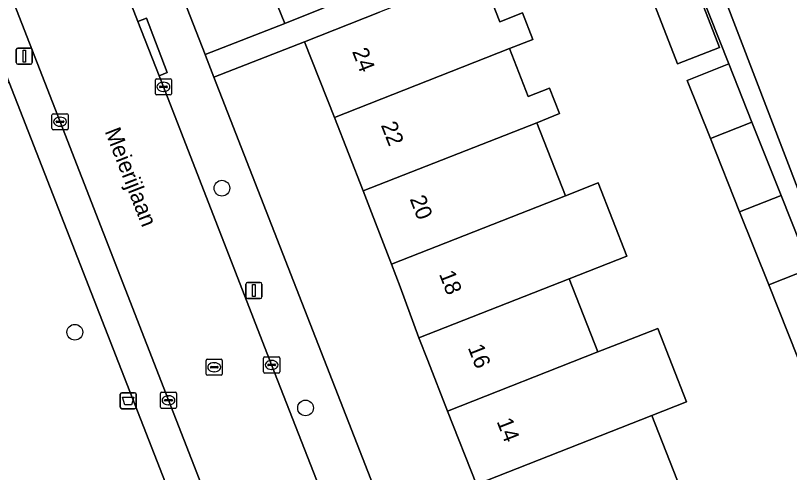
# Model space of a CAD drawing. Extents: x 159680 to 160786, y 387323 to 388340.
# Drawn here: x 160044.77 to 160092.86, y 387434.59 to 387462.98 of the extents above; entities that cross this region are included whole.
import ezdxf

# ---------------------------------------------------------------- set-up
doc = ezdxf.new("R2010")
doc.units = 0
for name, color, linetype in [('IMGEO_Afvalbak', 7, 'Continuous'), ('IMGEO_Boom', 7, 'Continuous'), ('IMGEO_Erf', 7, 'Continuous'), ('IMGEO_Groenvoorziening', 7, 'Continuous'), ('IMGEO_Kolk', 7, 'Continuous'), ('IMGEO_Lichtmast', 7, 'Continuous'), ('IMGEO_Muur', 7, 'Continuous'), ('IMGEO_Openbare_ruimte_label', 7, 'Continuous'), ('IMGEO_Pand', 7, 'Continuous'), ('IMGEO_Pand_nummerreeks', 7, 'Continuous'), ('IMGEO_Rijbaan_lokaal_open', 7, 'Continuous'), ('IMGEO_Rioolput', 7, 'Continuous'), ('IMGEO_Voetpad_open', 7, 'Continuous')]:
    doc.layers.add(name, color=color, linetype=linetype)

msp = doc.modelspace()

# ---------------------------------------------------------------- linework, layer by layer
at = {"layer": 'IMGEO_Afvalbak'}
for p, q in [((160051.283, 387438.647), (160051.283, 387439.447)), ((160051.283, 387439.447), (160051.283, 387438.647)), ((160051.383, 387439.547), (160052.173, 387439.547)), ((160052.173, 387439.547), (160051.383, 387439.547)), ((160052.273, 387439.447), (160052.273, 387438.647)), ((160052.273, 387438.647), (160052.273, 387439.447)), ((160052.173, 387438.547), (160051.383, 387438.547)), ((160051.383, 387438.547), (160052.173, 387438.547))]:
    msp.add_line(p, q, dxfattribs=at)
msp.add_lwpolyline([(160051.426, 387439.261), (160052.13, 387439.261), (160051.981, 387438.791), (160051.575, 387438.791), (160051.426, 387439.261)], dxfattribs=at)
for centre, start, end in [((160051.383, 387439.447), 90, 180), ((160051.383, 387439.447), 90, 180), ((160052.173, 387439.447), 0, 90), ((160052.173, 387439.447), 360, 90), ((160051.383, 387438.647), 180, 270), ((160051.383, 387438.647), 180, 270), ((160052.173, 387438.647), 270, 0), ((160052.173, 387438.647), 270, 0)]:
    msp.add_arc(centre, 0.1, start, end, dxfattribs=at)
at = {"layer": 'IMGEO_Boom'}
for centre in [(160057.598, 387452.249), (160048.46, 387443.302), (160062.793, 387438.599)]:
    msp.add_circle(centre, 0.489, dxfattribs=at)
at = {"layer": 'IMGEO_Erf'}
for points in [[(160098.383, 387501.774), (160097.114, 387501.273), (160093.888, 387500), (160077.508, 387493.535), (160099.139, 387437.225), (160113.969, 387443.3), (160122.048, 387446.454)], [(160048.858, 387480.25), (160049.768, 387477.92), (160056.549, 387460.554), (160061.498, 387462.487), (160060.179, 387465.75), (160064.86, 387467.643), (160067.322, 387468.638), (160068.641, 387465.375), (160078.623, 387469.308), (160084.48, 387471.518), (160084.359, 387471.814), (160081.27, 387470.546), (160080.225, 387473.092), (160083.461, 387474.421), (160080.976, 387480.847)], [(160093.377, 387441.71), (160091.567, 387446.251), (160089.758, 387450.79), (160087.948, 387455.331), (160086.507, 387458.947), (160089.08, 387459.972), (160084.957, 387470.364)], [(160073.663, 387465.65), (160074.866, 387462.591), (160076.272, 387463.144), (160076.921, 387461.494), (160075.46, 387460.919), (160076.629, 387457.948), (160077.938, 387458.463), (160078.558, 387456.886), (160077.156, 387456.299), (160078.932, 387451.781), (160080.968, 387452.582), (160082.759, 387448.036), (160079.171, 387446.623), (160080.959, 387442.075), (160082.508, 387442.685), (160084.67, 387443.536), (160086.46, 387438.988), (160084.296, 387438.136), (160086.084, 387433.588), (160087.805, 387429.211), (160087.872, 387429.04), (160088.826, 387426.615), (160094.321, 387428.778)], [(160073.404, 387433.849), (160071.616, 387438.397), (160070.387, 387441.537), (160069.833, 387442.947), (160068.677, 387446.123), (160068.125, 387447.526), (160066.897, 387450.749), (160066.37, 387452.088), (160064.582, 387456.636), (160062.728, 387461.35), (160057.097, 387459.151), (160078.812, 387403.541), (160078.867, 387403.411)]]:
    msp.add_lwpolyline(points, dxfattribs=at)
msp.add_lwpolyline([(160084.194, 387464.358), (160082.449, 387468.851), (160085.063, 387469.866), (160086.804, 387465.385), (160088.515, 387460.98), (160085.901, 387459.965)], close=True, dxfattribs=at)
at = {"layer": 'IMGEO_Groenvoorziening'}
msp.add_lwpolyline([(160070.819, 387394.075), (160067.983, 387398.729), (160067.343, 387400.014), (160044.382, 387458.812), (160038.002, 387456.318), (160019.905, 387500)], dxfattribs=at)
at = {"layer": 'IMGEO_Kolk'}
for p, q in [((160053.464, 387458.119), (160053.464, 387458.971)), ((160053.539, 387459.045), (160054.391, 387459.045)), ((160054.465, 387458.971), (160054.465, 387458.119)), ((160053.723, 387458.539), (160053.723, 387458.551)), ((160054.161, 387458.502), (160053.763, 387458.502)), ((160053.766, 387458.588), (160054.164, 387458.588)), ((160053.952, 387458.825), (160053.977, 387458.825)), ((160054.207, 387458.551), (160054.207, 387458.539)), ((160054.391, 387458.045), (160053.539, 387458.045)), ((160053.975, 387458.265), (160053.95, 387458.265)), ((160047.042, 387455.951), (160047.042, 387456.803)), ((160047.117, 387456.877), (160047.969, 387456.877)), ((160047.53, 387456.657), (160047.555, 387456.657)), ((160048.043, 387456.803), (160048.043, 387455.951)), ((160047.301, 387456.371), (160047.301, 387456.383)), ((160047.739, 387456.334), (160047.341, 387456.334)), ((160047.344, 387456.42), (160047.742, 387456.42)), ((160047.553, 387456.097), (160047.528, 387456.097)), ((160047.785, 387456.383), (160047.785, 387456.371)), ((160047.969, 387455.877), (160047.117, 387455.877)), ((160060.185, 387440.843), (160060.185, 387441.695)), ((160060.26, 387441.769), (160061.112, 387441.769)), ((160060.673, 387441.549), (160060.698, 387441.549)), ((160061.186, 387441.695), (160061.186, 387440.843)), ((160060.444, 387441.263), (160060.444, 387441.275)), ((160060.882, 387441.226), (160060.484, 387441.226)), ((160060.487, 387441.312), (160060.885, 387441.312)), ((160060.928, 387441.275), (160060.928, 387441.263)), ((160061.112, 387440.769), (160060.26, 387440.769)), ((160060.696, 387440.989), (160060.671, 387440.989)), ((160053.778, 387438.649), (160053.778, 387439.501)), ((160053.853, 387439.575), (160054.705, 387439.575)), ((160054.08, 387439.118), (160054.478, 387439.118)), ((160054.266, 387439.355), (160054.291, 387439.355)), ((160054.779, 387439.501), (160054.779, 387438.649)), ((160054.037, 387439.069), (160054.037, 387439.081)), ((160054.475, 387439.032), (160054.077, 387439.032)), ((160054.289, 387438.795), (160054.264, 387438.795)), ((160054.521, 387439.081), (160054.521, 387439.069)), ((160054.705, 387438.575), (160053.853, 387438.575))]:
    msp.add_line(p, q, dxfattribs=at)
for points in [[(160053.464, 387458.119), (160053.464, 387458.971)], [(160053.539, 387459.045), (160054.391, 387459.045)], [(160054.465, 387458.971), (160054.465, 387458.119)], [(160054.391, 387458.045), (160053.539, 387458.045)], [(160047.042, 387455.951), (160047.042, 387456.803)], [(160047.117, 387456.877), (160047.969, 387456.877)], [(160048.043, 387456.803), (160048.043, 387455.951)], [(160047.969, 387455.877), (160047.117, 387455.877)], [(160060.185, 387440.843), (160060.185, 387441.695)], [(160060.26, 387441.769), (160061.112, 387441.769)], [(160061.186, 387441.695), (160061.186, 387440.843)], [(160061.112, 387440.769), (160060.26, 387440.769)], [(160053.778, 387438.649), (160053.778, 387439.501)], [(160053.853, 387439.575), (160054.705, 387439.575)], [(160054.779, 387439.501), (160054.779, 387438.649)], [(160054.705, 387438.575), (160053.853, 387438.575)]]:
    msp.add_lwpolyline(points, dxfattribs=at)
for centre, radius, start, end in [((160053.541, 387458.969), 0.0765, 91.552, 178.448), ((160053.541, 387458.969), 0.0765, 91.552, 178.448), ((160054.389, 387458.969), 0.0765, 1.552, 88.448), ((160054.389, 387458.969), 0.0765, 1.552, 88.448), ((160053.763, 387458.548), 0.0403, 85.8775, 175.7526), ((160053.76, 387458.538), 0.0366, 178.938, 274.7102), ((160054.164, 387458.545), 0.043, 264.8664, 352.4533), ((160054.168, 387458.55), 0.0386, 1.7309, 96.639), ((160053.541, 387458.121), 0.0765, 181.552, 268.448), ((160053.541, 387458.121), 0.0765, 181.552, 268.448), ((160054.389, 387458.121), 0.0765, 271.552, 358.448), ((160054.389, 387458.121), 0.0765, 271.552, 358.448), ((160047.119, 387456.801), 0.0765, 91.552, 178.448), ((160047.119, 387456.801), 0.0765, 91.552, 178.448), ((160047.967, 387456.801), 0.0765, 1.552, 88.448), ((160047.967, 387456.801), 0.0765, 1.552, 88.448), ((160047.119, 387455.953), 0.0765, 181.552, 268.448), ((160047.119, 387455.953), 0.0765, 181.552, 268.448), ((160047.341, 387456.38), 0.0403, 85.8775, 175.7526), ((160047.338, 387456.37), 0.0366, 178.938, 274.7102), ((160047.742, 387456.377), 0.043, 264.8664, 352.4533), ((160047.746, 387456.382), 0.0386, 1.7309, 96.639), ((160047.967, 387455.953), 0.0765, 271.552, 358.448), ((160047.967, 387455.953), 0.0765, 271.552, 358.448), ((160060.262, 387441.693), 0.0765, 91.552, 178.448), ((160060.262, 387441.693), 0.0765, 91.552, 178.448), ((160061.11, 387441.693), 0.0765, 1.552, 88.448), ((160061.11, 387441.693), 0.0765, 1.552, 88.448), ((160060.484, 387441.272), 0.0403, 85.8775, 175.7526), ((160060.481, 387441.262), 0.0366, 178.938, 274.7102), ((160060.885, 387441.269), 0.043, 264.8664, 352.4533), ((160060.889, 387441.274), 0.0386, 1.7309, 96.639), ((160060.262, 387440.845), 0.0765, 181.552, 268.448), ((160060.262, 387440.845), 0.0765, 181.552, 268.448), ((160061.11, 387440.845), 0.0765, 271.552, 358.448), ((160061.11, 387440.845), 0.0765, 271.552, 358.448), ((160053.855, 387439.499), 0.0765, 91.552, 178.448), ((160053.855, 387439.499), 0.0765, 91.552, 178.448), ((160054.077, 387439.078), 0.0403, 85.8775, 175.7526), ((160054.482, 387439.08), 0.0386, 1.7309, 96.639), ((160054.703, 387439.499), 0.0765, 1.552, 88.448), ((160054.703, 387439.499), 0.0765, 1.552, 88.448), ((160053.855, 387438.651), 0.0765, 181.552, 268.448), ((160053.855, 387438.651), 0.0765, 181.552, 268.448), ((160054.074, 387439.068), 0.0366, 178.938, 274.7102), ((160054.478, 387439.075), 0.043, 264.8664, 352.4533), ((160054.703, 387438.651), 0.0765, 271.552, 358.448), ((160054.703, 387438.651), 0.0765, 271.552, 358.448)]:
    msp.add_arc(centre, radius, start, end, dxfattribs=at)
for centre, major_axis, ratio, start_param, end_param in [((160053.951, 387458.545), (-0.387, 0.002), 0.722429, 4.712389, 7.853982), ((160053.976, 387458.545), (-0.39, 0.002), 0.717154, 1.570796, 4.712389), ((160047.529, 387456.377), (-0.387, 0.002), 0.722429, 4.712389, 7.853982), ((160047.554, 387456.377), (-0.39, 0.002), 0.717154, 1.570796, 4.712389), ((160060.672, 387441.269), (-0.387, 0.002), 0.722429, 4.712389, 7.853982), ((160060.697, 387441.269), (-0.39, 0.002), 0.717154, 1.570796, 4.712389), ((160054.265, 387439.075), (-0.387, 0.002), 0.722429, 4.712389, 7.853982), ((160054.29, 387439.075), (-0.39, 0.002), 0.717154, 1.570796, 4.712389)]:
    msp.add_ellipse(centre, major_axis=major_axis, ratio=ratio, start_param=start_param, end_param=end_param, dxfattribs=at)
at = {"layer": 'IMGEO_Lichtmast'}
for p, q in [((160044.826, 387460.054), (160044.826, 387460.854)), ((160044.826, 387460.854), (160044.826, 387460.054)), ((160044.926, 387460.954), (160045.716, 387460.954)), ((160045.716, 387460.954), (160044.926, 387460.954)), ((160045.816, 387460.854), (160045.816, 387460.054)), ((160045.816, 387460.054), (160045.816, 387460.854)), ((160045.716, 387459.954), (160044.926, 387459.954)), ((160044.926, 387459.954), (160045.716, 387459.954)), ((160059.187, 387446.395), (160059.977, 387446.395)), ((160059.977, 387446.395), (160059.187, 387446.395)), ((160059.087, 387445.495), (160059.087, 387446.295)), ((160059.087, 387446.295), (160059.087, 387445.495)), ((160060.077, 387446.295), (160060.077, 387445.495)), ((160060.077, 387445.495), (160060.077, 387446.295)), ((160059.977, 387445.395), (160059.187, 387445.395)), ((160059.187, 387445.395), (160059.977, 387445.395))]:
    msp.add_line(p, q, dxfattribs=at)
for points in [[(160045.246, 387460.829), (160045.396, 387460.829), (160045.396, 387460.079), (160045.246, 387460.079), (160045.246, 387460.829)], [(160059.507, 387446.27), (160059.657, 387446.27), (160059.657, 387445.52), (160059.507, 387445.52), (160059.507, 387446.27)]]:
    msp.add_lwpolyline(points, dxfattribs=at)
for centre, start, end in [((160044.926, 387460.854), 90, 180), ((160044.926, 387460.854), 90, 180), ((160045.716, 387460.854), 0, 90), ((160045.716, 387460.854), 360, 90), ((160044.926, 387460.054), 180, 270), ((160044.926, 387460.054), 180, 270), ((160045.716, 387460.054), 270, 0), ((160045.716, 387460.054), 270, 0), ((160059.187, 387446.295), 90, 180), ((160059.187, 387446.295), 90, 180), ((160059.977, 387446.295), 0, 90), ((160059.977, 387446.295), 360, 90), ((160059.187, 387445.495), 180, 270), ((160059.187, 387445.495), 180, 270), ((160059.977, 387445.495), 270, 0), ((160059.977, 387445.495), 270, 0)]:
    msp.add_arc(centre, 0.1, start, end, dxfattribs=at)
at = {"layer": 'IMGEO_Muur'}
msp.add_lwpolyline([(160049.768, 387477.92), (160056.549, 387460.554), (160056.572, 387460.495)], dxfattribs=at)
at = {"layer": 'IMGEO_Pand'}
for points in [[(160064.86, 387467.643), (160060.179, 387465.75), (160061.498, 387462.487), (160066.142, 387464.364)], [(160076.272, 387463.144), (160074.866, 387462.591), (160073.663, 387465.65), (160067.382, 387463.18), (160062.728, 387461.35), (160064.582, 387456.636), (160075.46, 387460.919), (160076.921, 387461.494)], [(160086.804, 387465.385), (160084.194, 387464.358), (160085.901, 387459.965), (160088.515, 387460.98)], [(160078.558, 387456.886), (160077.938, 387458.463), (160076.629, 387457.948), (160075.46, 387460.919), (160064.582, 387456.636), (160066.37, 387452.088), (160077.156, 387456.299)], [(160087.948, 387455.331), (160090.525, 387456.346), (160089.08, 387459.972), (160086.507, 387458.947)], [(160066.37, 387452.088), (160066.897, 387450.749), (160068.125, 387447.526), (160078.932, 387451.781), (160077.156, 387456.299)], [(160090.525, 387456.346), (160087.948, 387455.331), (160089.758, 387450.79), (160092.335, 387451.805)], [(160080.968, 387452.582), (160078.932, 387451.781), (160068.125, 387447.526), (160068.677, 387446.123), (160069.833, 387442.947), (160079.171, 387446.623), (160082.759, 387448.036)], [(160092.335, 387451.805), (160089.758, 387450.79), (160091.567, 387446.251), (160094.144, 387447.266)], [(160094.144, 387447.266), (160091.567, 387446.251), (160093.377, 387441.71), (160095.954, 387442.725)], [(160079.171, 387446.623), (160069.833, 387442.947), (160070.387, 387441.537), (160071.616, 387438.397), (160080.959, 387442.075)], [(160086.46, 387438.988), (160084.67, 387443.536), (160082.508, 387442.685), (160080.959, 387442.075), (160071.616, 387438.397), (160073.404, 387433.849), (160084.296, 387438.136)], [(160073.404, 387433.849), (160075.193, 387429.301), (160086.084, 387433.588), (160084.296, 387438.136)]]:
    msp.add_lwpolyline(points, close=True, dxfattribs=at)
at = {"layer": 'IMGEO_Rijbaan_lokaal_open'}
for points in [[(160046.513, 387477.713), (160045.765, 387479.734), (160039.549, 387495.628), (160039.516, 387495.711), (160039.429, 387495.946), (160033.273, 387511.651), (160031.95, 387515.027), (160031.202, 387516.934), (160024.093, 387535.131), (160021.109, 387542.72), (160014.836, 387540.165), (160017.868, 387532.491), (160033.182, 387493.23), (160040.063, 387475.562), (160047.543, 387456.377), (160054.279, 387439.075), (160061.763, 387419.918), (160069.174, 387400.967), (160069.426, 387400.286), (160069.653, 387399.763)], [(160075.587, 387403.186), (160068.134, 387422.235), (160060.686, 387441.269), (160053.965, 387458.545), (160053.696, 387459.237), (160052.383, 387462.613), (160046.513, 387477.713)]]:
    msp.add_lwpolyline(points, dxfattribs=at)
at = {"layer": 'IMGEO_Rioolput'}
for p, q in [((160056.619, 387440.703), (160056.619, 387441.555)), ((160056.694, 387441.629), (160057.546, 387441.629)), ((160057.62, 387441.555), (160057.62, 387440.703)), ((160056.878, 387441.123), (160056.878, 387441.135)), ((160057.316, 387441.086), (160056.918, 387441.086)), ((160056.921, 387441.172), (160057.319, 387441.172)), ((160057.107, 387441.409), (160057.132, 387441.409)), ((160057.362, 387441.135), (160057.362, 387441.123)), ((160057.546, 387440.629), (160056.694, 387440.629)), ((160057.13, 387440.849), (160057.105, 387440.849))]:
    msp.add_line(p, q, dxfattribs=at)
for points in [[(160056.619, 387440.703), (160056.619, 387441.555)], [(160056.694, 387441.629), (160057.546, 387441.629)], [(160057.62, 387441.555), (160057.62, 387440.703)], [(160057.546, 387440.629), (160056.694, 387440.629)]]:
    msp.add_lwpolyline(points, dxfattribs=at)
for centre, radius, start, end in [((160056.696, 387441.553), 0.0765, 91.552, 178.448), ((160056.696, 387441.553), 0.0765, 91.552, 178.448), ((160057.544, 387441.553), 0.0765, 1.552, 88.448), ((160057.544, 387441.553), 0.0765, 1.552, 88.448), ((160056.918, 387441.132), 0.0403, 85.8775, 175.7526), ((160056.915, 387441.122), 0.0366, 178.938, 274.7102), ((160057.319, 387441.129), 0.043, 264.8664, 352.4533), ((160057.323, 387441.134), 0.0386, 1.7309, 96.639), ((160056.696, 387440.705), 0.0765, 181.552, 268.448), ((160056.696, 387440.705), 0.0765, 181.552, 268.448), ((160057.544, 387440.705), 0.0765, 271.552, 358.448), ((160057.544, 387440.705), 0.0765, 271.552, 358.448)]:
    msp.add_arc(centre, radius, start, end, dxfattribs=at)
for centre, major_axis, ratio, start_param, end_param in [((160057.106, 387441.129), (-0.387, 0.002), 0.722429, 4.712389, 7.853982), ((160057.131, 387441.129), (-0.39, 0.002), 0.717154, 1.570796, 4.712389)]:
    msp.add_ellipse(centre, major_axis=major_axis, ratio=ratio, start_param=start_param, end_param=end_param, dxfattribs=at)
at = {"layer": 'IMGEO_Voetpad_open'}
for points in [[(160014.836, 387540.165), (160013.589, 387543.411), (160011.086, 387549.84), (160003.933, 387567.986), (159996.839, 387586.222), (159994.039, 387593.358), (159993.669, 387594.324), (159991.895, 387593.661), (160000, 387572.683), (160000.641, 387571.024), (160001.69, 387568.209), (160003.634, 387562.989), (160009.216, 387548.634), (160011.162, 387543.629), (160011.828, 387541.916), (160012.723, 387539.639), (160025.253, 387507.75), (160028.282, 387500), (160044.382, 387458.812), (160067.343, 387400.014), (160067.983, 387398.729), (160070.819, 387394.075)], [(160069.653, 387399.763), (160069.426, 387400.286), (160069.174, 387400.967), (160061.763, 387419.918), (160054.279, 387439.075), (160047.543, 387456.377), (160040.063, 387475.562), (160033.182, 387493.23), (160017.868, 387532.491), (160014.836, 387540.165)], [(160099.139, 387437.225), (160077.508, 387493.535)], [(160057.097, 387459.151), (160056.572, 387460.495), (160056.549, 387460.554), (160049.768, 387477.92), (160048.858, 387480.25), (160046.649, 387485.093)], [(160045.765, 387479.734), (160046.513, 387477.713), (160052.383, 387462.613), (160052.903, 387462.813), (160054.206, 387459.433), (160053.696, 387459.237), (160053.965, 387458.545), (160060.686, 387441.269), (160068.134, 387422.235), (160075.587, 387403.186)], [(160084.957, 387470.364), (160089.08, 387459.972), (160090.525, 387456.346), (160092.335, 387451.805), (160094.144, 387447.266)], [(160066.142, 387464.364), (160061.498, 387462.487), (160056.549, 387460.554), (160056.572, 387460.495), (160057.097, 387459.151), (160062.728, 387461.35), (160067.382, 387463.18)], [(160080.631, 387399.313), (160078.867, 387403.411), (160078.812, 387403.541), (160057.097, 387459.151)]]:
    msp.add_lwpolyline(points, dxfattribs=at)
msp.add_lwpolyline([(160052.903, 387462.813), (160052.383, 387462.613), (160053.696, 387459.237), (160054.206, 387459.433)], close=True, dxfattribs=at)

# ---------------------------------------------------------------- texts
at = {"layer": 'IMGEO_Openbare_ruimte_label'}
msp.add_text('Meierijlaan', height=1, rotation=291.4077, dxfattribs=at).set_placement((160050.306, 387455.783))
at = {"layer": 'IMGEO_Pand_nummerreeks'}
for s, rotation, p in [('24', 291.3425, (160065.67, 387460.747)), ('22', 291.3425, (160067.458, 387456.17)), ('20', 291.3407, (160069.249, 387451.585)), ('18', 291.3425, (160071.071, 387446.921)), ('16', 291.3425, (160072.86, 387442.344)), ('14', 291.3425, (160074.649, 387437.764))]:
    msp.add_text(s, height=1, rotation=rotation, dxfattribs=at).set_placement(p)

doc.saveas('drawing.dxf')
